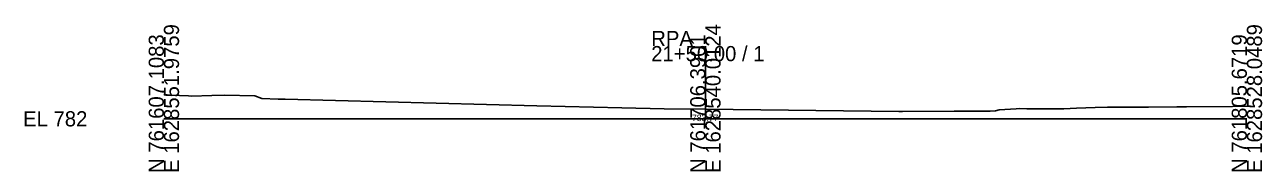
# Model space of a CAD drawing. Extents: x -26 to 203, y 990 to 7517.
# Drawn here: x -25.7 to 202.8, y 6990.3 to 7017.4 of the extents above; entities that cross this region are included whole.
import ezdxf

# ---------------------------------------------------------------- set-up
doc = ezdxf.new("R2010")
doc.units = 0
for name, color, linetype in [('Exist Cross Section Cell', 7, 'Continuous'), ('Exist XS Center Line Elevation Label', 7, 'Continuous'), ('Exist XS Ground Line', 7, 'Continuous')]:
    doc.layers.add(name, color=color, linetype=linetype)

msp = doc.modelspace()

# ---------------------------------------------------------------- linework, layer by layer
at = {"layer": 'Exist Cross Section Cell'}
for p, q in [((100, 7000), (100, 7013.44)), ((0, 7000), (100, 7000)), ((100, 7000), (200, 7000))]:
    msp.add_line(p, q, dxfattribs=at)
at = {"layer": 'Exist XS Ground Line'}
for p, q in [((0, 7004.48), (1.21, 7004.34)), ((1.21, 7004.34), (4.57, 7004.22)), ((4.57, 7004.22), (5.1, 7004.21)), ((5.1, 7004.21), (8.88, 7004.29)), ((8.88, 7004.29), (11.18, 7004.36)), ((11.18, 7004.36), (16.82, 7004.23)), ((16.82, 7004.23), (18.1, 7003.73)), ((18.1, 7003.73), (21.08, 7003.65)), ((21.08, 7003.65), (22.4, 7003.61)), ((22.4, 7003.61), (68.85, 7002.39)), ((68.85, 7002.39), (84.6, 7002)), ((188.83, 7002.23), (197.33, 7002.3)), ((197.33, 7002.3), (200, 7002.34)), ((84.6, 7002), (92.4, 7001.87)), ((92.4, 7001.87), (100, 7001.77)), ((100, 7001.77), (135.71, 7001.32)), ((135.71, 7001.32), (136.4, 7001.33)), ((136.4, 7001.33), (145.96, 7001.38)), ((145.96, 7001.38), (147.97, 7001.39)), ((147.97, 7001.39), (148.56, 7001.39)), ((148.56, 7001.39), (152.61, 7001.41)), ((152.61, 7001.41), (153.59, 7001.46)), ((153.59, 7001.46), (154.23, 7001.63)), ((154.23, 7001.63), (157.41, 7001.84)), ((157.41, 7001.84), (157.94, 7001.88)), ((157.94, 7001.88), (159.36, 7001.86)), ((159.36, 7001.86), (165.65, 7001.86)), ((165.65, 7001.86), (166.19, 7001.87)), ((166.19, 7001.87), (168.54, 7001.96)), ((168.54, 7001.96), (172, 7002.11)), ((172, 7002.11), (174.28, 7002.12)), ((174.28, 7002.12), (181.85, 7002.16)), ((181.85, 7002.16), (187.07, 7002.2)), ((187.07, 7002.2), (188.83, 7002.23))]:
    msp.add_line(p, q, dxfattribs=at)

# ---------------------------------------------------------------- texts
at = {"layer": 'Exist Cross Section Cell'}
for s, p in [('E 1628551.9759', (2.8, 6990)), ('E 1628540.0124', (102.8, 6990)), ('E 1628528.0489', (202.8, 6990)), ('N 761607.1083', (0, 6990)), ('N 761706.3901', (100, 6990)), ('N 761805.6719', (200, 6990))]:
    msp.add_text(s, height=2.8, rotation=90, dxfattribs=at).set_placement(p)
for s, p in [('RPA', (90, 7013.44)), ('21+50.00 / 1', (90, 7010.64)), ('EL 782', (-26, 6998.6))]:
    msp.add_text(s, height=2.8, dxfattribs=at).set_placement(p)
at = {"layer": 'Exist XS Center Line Elevation Label'}
msp.add_text('783.77', height=1.2, dxfattribs=at).set_placement((97.51, 6999.57))

doc.saveas('drawing.dxf')
